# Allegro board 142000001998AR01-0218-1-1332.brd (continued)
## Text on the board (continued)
User.45: CONN16 | HSB1 | U31 | 03 | 02 | R848 | R150 | R908 | 2 | R707 | 11 | 10 | 21 | 20 | C54 | R147 | H* | C453 | C399 | R135 | R132 | C567 | C570 | C590 | C452 | C398 | R1086 | C58 | 74 | 75 | R152 | R157 | R156 | R672 | R677 | R687 | R651 | R660 | R644 | C605 | R722 | C276 | C277 | C61 | C604 | R721 | R663 | R673 | C544 | C319 | R563 | C396 | C913 | C517 | U34 | R1088 | C318 | L37 | C627 | C464 | R577 | R541 | R542 | R536 | C648 | C507 | R611 | C629 | C631 | C634 | C505 | C647 | R803 | C500 | C502 | R608 | C120 | C119 | C116 | C117 | C115 | R694 | C571 | C591 | R727 | C608 | C585 | C939 | C938 | C942 | C636 | R748 | C961 | C944 | C154 | R555 | C930 | C966 | C934 | C936 | C937 | C973 | C972 | R583 | R587 | R589 | R590 | R597 | C402 | R561 | R881 | R868 | C508 | TP34 | R715 | TP36 | C291 | R628 | R640 | C515 | C455 | C440 | C462 | C472 | C593 | R753 | L35 | C327 | R630 | Q9 | C388 | L30 | Q10 | R508 | R509 | Q1 | C456 | C509 | R617 | R586 | C342 | TP30 | R502 | C372 | C384 | C457 | C971 | C379 | C417 | R632 | R613 | C911 | R639 | R785 | R615 | C976 | D1 | R634 | TP31 | R642 | R625 | R506 | TP20 | R635 | R499 | R578 | C497 | R624 | R456 | C461 | Q14 | R633 | C449 | R638 | C503 | TP15 | R599 | R600 | R604 | R605 | C289 | TP16 | C292 | R452 | R518 | R485 | R483 | R448 | R439 | C493 | C496 | TP37 | R790 | C504 | C506 | C501 | U36 | C481 | C522 | C529 | C526 | TP35 | R432 | R449 | R443 | R458 | R878 | R877 | Q13 | R470 | R467 | R471 | R481 | C465 | R516 | C510 | C511 | C512 | C378 | C387 | C421 | C429 | Q12 | C401 | C446 | R454 | R488 | C466 | R733 | R741 | C606 | C360 | C345 | R557 | R431 | R559 | C400 | C407 | R462 | R521 | R438 | R777 | R566 | TP23 | TP24 | C377 | C498 | C476 | C485 | C488 | C494 | R571 | R459 | R740 | R744 | R724 | R474 | R430 | R562 | C454 | C431 | R444 | R463 | C633 | C635 | R445 | R451 | R70 | U32 | R723 | R429 | C595 | C597 | R447 | R460 | R780 | C565 | R693 | C572 | C530 | C539 | C549 | R729 | R758 | R743 | C325 | R543 | C525 | C419 | C139 | C406 | C441 | C338 | C322 | Q7 | C305 | C301 | C317 | C370 | C330 | C458 | C310 | C362 | C323 | C373 | C389 | C405 | C420 | R580 | C415 | R574 | R756 | C463 | C386 | C404 | C397 | C430 | C416 | R649 | C365 | C326 | C260 | C614 | C336 | C625 | R742 | C293 | C489 | C484 | C306 | R656 | C335 | C312 | C603 | R912 | R913 | R914 | R915 | R916 | C518 | C519 | C448 | C460 | C638 | C602 | C382 | R560 | R565 | R568 | R564 | L36 | R579 | R943 | C589 | C592 | R576 | R581 | R585 | C564 | C490 | R918 | R726 | U45 | R648 | C908 | R700 | C588 | U40 | R708 | R711 | C339 | R647 | R1069 | C369 | C376 | C403 | C410 | C450 | C442 | R917 | C574 | C575 | U41 | R952 | R953 | R754 | R433 | R646 | R652 | C613 | C459 | C467 | C473 | C483 | R540 | R937 | R940 | R938 | R709 | C383 | C395 | C353 | C371 | C408 | R939 | C423 | C439 | R1056 | C340 | C354 | R941 | C267 | C269 | C271 | Q11 | Q8 | CONN14 | C637 | R791 | R792 | R786 | R788 | C272 | C273 | 5 | 165 | 71 | 15 | 25 | 45 | 35 | 175 | 65 | 55 | 85 | 95 | 73 | 125 | 135 | 145 | 195 | 203 | 185 | 105 | 115 | 155 | 80 | 90 | 30 | 40 | 50 | 60 | 70 | 100 | 110 | 120 | 130 | 140 | 150 | 170 | 180 | 190 | 204 | 160 | 119 | CONN13 | CONN15 | R671 | C65 | R413 | C64 | R670 | C480 | C356 | R412 | R669 | C478 | R668 | R411 | R661 | R911 | C358 | R686 | R410 | R151 | R909 | R674 | R409 | C414 | C438 | R666 | C413 | C437 | R706 | R653 | R408 | R705 | R650 | R910 | R641 | R407 | R133 | R869 | R704 | C282 | R230 | R665 | R703 | R149 | C281 | R664 | R702 | R695 | R406 | R696 | C412 | C436 | R405 | C411 | C435 | R404 | R718 | C477 | R717 | C479 | R159 | R843 | R158 | C357 | R716 | C355 | R572 | R1082 | C914 | C915 | C298 | R629 | C516 | C514 | C290 | C513 | R556 | R954 | R249 | R955 | R612 | R573 | C375 | R631 | R538 | C443 | R1083 | R575 | R537 | C445 | R567 | U35 | R1045 | C41 | C611 | C610 | R119 | C609 | R120 | C612 | R731 | C275 | R732 | C624 | C626 | R697 | R468 | R465 | C623 | C247 | C246 | C573 | C622 | C621 | C927 | C925 | C620 | C332 | C619 | C929 | R550 | C926 | R1001 | C245 | C943 | R999 | C933 | C960 | C928 | C244 | C945 | C941 | C931 | C959 | R602 | R800 | C935 | R601 | R618 | R619 | R558 | R455 | R1050 | C560 | R1049 | R745 | C559 | R435 | C29 | C558 | R427 | L32 | R627 | R751 | C555 | R934 | C311 | R522 | C546 | Q16 | C316 | R932 | TP32 | C548 | TP28 | C28 | C315 | C279 | R519 | R784 | C499 | TP29 | C314 | R783 | C313 | C434 | R928 | C300 | C433 | TP17 | R598 | R926 | R749 | R927 | R637 | C286 | C299 | C418 | R925 | R582 | R935 | R515 | R795 | C409 | R930 | R924 | R936 | TP18 | R535 | R569 | R929 | C557 | R906 | R487 | R584 | R923 | C263 | R933 | R457 | R486 | R507 | R501 | R626 | C556 | R596 | R595 | R594 | R787 | C547 | R752 | R610 | R667 | R779 | R614 | R609 | C274 | R778 | R616 | R636 | R643 | R523 | R505 | C492 | R645 | R478 | R520 | R480 | R479 | R879 | R440 | R464 | C482 | TP22 | R676 | R659 | R658 | R675 | TP26 | R657 | TP25 | TP14 | TP21 | R553 | TP19 | C607 | R490 | R131 | C368 | C581 | R720 | C367 | C580 | C495 | R489 | R719 | C366 | C579 | R623 | R475 | C578 | R622 | C364 | C285 | C577 | R621 | R554 | R517 | C632 | C576 | C363 | C540 | R747 | R500 | R746 | C538 | C537 | R482 | R450 | C536 | C615 | R476 | C535 | C328 | C444 | R446 | C628 | C534 | R469 | R757 | R477 | C533 | R473 | C471 | R750 | C532 | C470 | C468 | C531 | R466 | R453 | R735 | R734 | R461 | C701 | C554 | C600 | C553 | C630 | C562 | C561 | C563 | R728 | C587 | R593 | C475 | R545 | C262 | C586 | TP33 | C374 | R546 | C474 | R592 | R544 | C584 | L33 | C594 | C583 | R755 | R710 | C582 | C344 | C385 | TP27 | C422 | C343 | C381 | R681 | R680 | C524 | C487 | R548 | C432 | C380 | C294 | R880 | C523 | R549 | C346 | L34 | C304 | C296 | C447 | C351 | C320 | R679 | C599 | C295 | C333 | C486 | R678 | C303 | C341 | C598 | R1090 | C334 | C543 | C394 | R1078 | C428 | C302 | C337 | C542 | C361 | C321 | R1080 | C393 | C541 | C427 | C331 | C297 | R1081 | C307 | L31 | C491 | C392 | R689 | C359 | R1091 | C324 | C426 | C639 | C352 | R688 | R1079 | C391 | R1057 | R655 | C329 | C349 | C425 | R551 | C390 | R654 | R547 | R1059 | C424 | C521 | R1061 | R570 | C348 | C520 | R730 | R1063 | C347 | R765 | R685 | R739 | U37 | R764 | R684 | R738 | C909 | R683 | R763 | C350 | R737 | R682 | R736 | R762 | R761 | R1067 | R528 | R760 | R527 | R725 | R699 | R1077 | R701 | R759 | R1072 | R526 | C566 | C596 | R776 | R525 | R1071 | R442 | R1065 | C569 | R947 | R1066 | R534 | R441 | R775 | C568 | R946 | R533 | R1070 | R607 | R603 | R769 | R532 | R948 | C528 | R531 | R768 | C167 | R691 | R416 | C527 | R530 | C278 | R690 | R415 | R437 | R767 | U33 | R529 | C552 | R414 | R942 | R436 | R766 | R421 | R498 | R774 | R420 | C551 | R773 | R419 | C550 | R606 | R772 | R497 | R418 | R771 | R424 | R492 | R423 | R491 | R422 | R494 | R426 | R493 | R425 | R496 | R417 | R495 | R1058 | R1060 | R1062 | R1064 | R1068 | R1089 | C964 | BA1 | C309 | C308 | FIGURE | SIZE | 8.0 | 10.0 | 12.0 | 16.0 | 28.0 | 43.0 | 134.0 | 30.0 | 35.0 | 40.0 | 44.0 | 45.0 | 48.0 | 59.0 | 63.0 | 71.0 | 125.0 | 138.0 | 166.0 | 177.0 | 44.0x28.0 | 189.0x126.0 | ALL UNITS ARE IN MILS | TOLERANCE | +3.0/-3.0 | +2.0/-2.0 | +3.0/-0.0 | PLATED | NON-PLATED | QTY | 1601 | 3627 | 86 | 4 | 1 | 3 | 8 | DRILL CHART: TOP to BOTTOM
